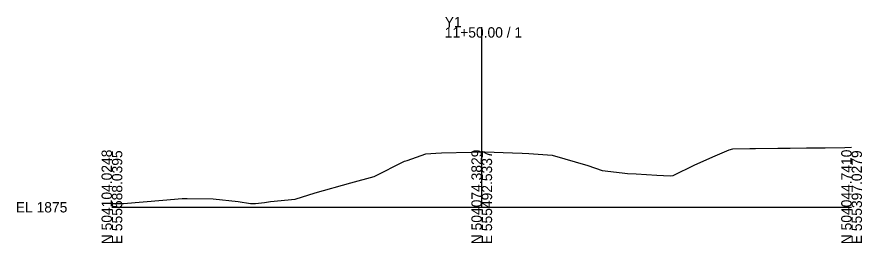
# Model space of a CAD drawing. Extents: x -26 to 203, y -10 to 5015.
# Drawn here: x -25.7 to 202.8, y 1490.3 to 1551.5 of the extents above; entities that cross this region are included whole.
import ezdxf

# ---------------------------------------------------------------- set-up
doc = ezdxf.new("R2010")
doc.units = 0
doc.layers.add('Exist Cross Section Cell', color=7, linetype='Continuous')
doc.layers.add('Exist XS Ground Line', color=7, linetype='Continuous')

msp = doc.modelspace()

# ---------------------------------------------------------------- linework, layer by layer
at = {"layer": 'Exist Cross Section Cell'}
for p, q in [((100, 1500), (100, 1548.71)), ((0, 1500), (100, 1500)), ((100, 1500), (200, 1500))]:
    msp.add_line(p, q, dxfattribs=at)
at = {"layer": 'Exist XS Ground Line'}
for p, q in [((163.14, 1513.95), (166.91, 1515.54)), ((166.91, 1515.54), (167.86, 1515.83)), ((167.86, 1515.83), (172.5, 1515.87)), ((172.5, 1515.87), (174.06, 1515.87)), ((174.06, 1515.87), (180.04, 1515.96)), ((180.04, 1515.96), (183.37, 1516)), ((183.37, 1516), (187.85, 1516.06)), ((187.85, 1516.06), (192.85, 1516.13)), ((192.85, 1516.13), (198.16, 1516.21)), ((198.16, 1516.21), (200, 1516.24)), ((79.79, 1512.65), (84.85, 1514.42)), ((84.85, 1514.42), (87.59, 1514.62)), ((87.59, 1514.62), (89.1, 1514.76)), ((89.1, 1514.76), (97.11, 1514.93)), ((97.11, 1514.93), (100, 1514.98)), ((100, 1514.98), (100.87, 1514.99)), ((100.87, 1514.99), (108.28, 1514.75)), ((108.28, 1514.75), (110.95, 1514.66)), ((110.95, 1514.66), (112.71, 1514.54)), ((112.71, 1514.54), (119.02, 1514.14)), ((119.02, 1514.14), (128.7, 1511.33)), ((157.59, 1511.45), (163.14, 1513.95)), ((70.95, 1508.3), (79.13, 1512.44)), ((79.13, 1512.44), (79.79, 1512.65)), ((128.7, 1511.33), (132.59, 1509.93)), ((151.78, 1508.6), (157.59, 1511.45)), ((132.59, 1509.93), (137.92, 1509.3)), ((137.92, 1509.3), (139.37, 1509.12)), ((139.37, 1509.12), (141.71, 1509.05)), ((141.71, 1509.05), (147.37, 1508.73)), ((147.37, 1508.73), (150.98, 1508.52)), ((150.98, 1508.52), (151.78, 1508.6)), ((54.97, 1503.87), (64.56, 1506.66)), ((64.56, 1506.66), (70.95, 1508.3)), ((49.55, 1502.17), (54.97, 1503.87)), ((3.11, 1501.06), (13.77, 1501.97)), ((13.77, 1501.97), (19.03, 1502.39)), ((19.03, 1502.39), (20.3, 1502.4)), ((20.3, 1502.4), (27.39, 1502.3)), ((27.39, 1502.3), (34.16, 1501.54)), ((34.16, 1501.54), (37.43, 1501.04)), ((41.29, 1501.31), (42.9, 1501.54)), ((42.9, 1501.54), (49.55, 1502.17)), ((0, 1501.04), (3.11, 1501.06)), ((37.43, 1501.04), (38.8, 1500.99)), ((38.8, 1500.99), (41.29, 1501.31))]:
    msp.add_line(p, q, dxfattribs=at)

# ---------------------------------------------------------------- texts
at = {"layer": 'Exist Cross Section Cell'}
for s, p in [('Y1', (90, 1548.71)), ('11+50.00 / 1', (90, 1545.91)), ('EL 1875', (-26, 1498.6))]:
    msp.add_text(s, height=2.8, dxfattribs=at).set_placement(p)
for s, p in [('N 504104.0248', (0, 1490)), ('E 555588.0395', (2.8, 1490)), ('N 504074.3829', (100, 1490)), ('E 555492.5337', (102.8, 1490)), ('N 504044.7410', (200, 1490)), ('E 555397.0279', (202.8, 1490))]:
    msp.add_text(s, height=2.8, rotation=90, dxfattribs=at).set_placement(p)

doc.saveas('drawing.dxf')
